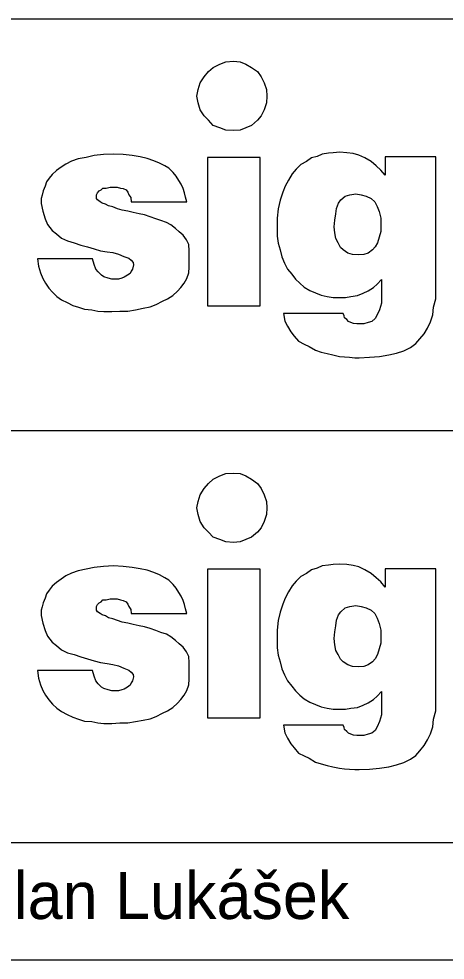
# Model space of a CAD drawing. Extents: x 2343 to 7744, y -5890 to 2050.
# Drawn here: x 6803.25 to 6821.39, y -5790 to -5750 of the extents above; entities that cross this region are included whole.
import ezdxf

# ---------------------------------------------------------------- set-up
doc = ezdxf.new("R2010")
doc.units = 0
for name, color, linetype in [('Info o rozpiskách', 7, 'Continuous'), ('popis', 7, 'Continuous'), ('Rozpiska_pole_6', 7, 'Continuous')]:
    doc.layers.add(name, color=color, linetype=linetype)

msp = doc.modelspace()

# ---------------------------------------------------------------- linework, layer by layer
at = {"layer": 'Info o rozpiskách'}
for points in [[(6812.382, -5751.803), (6812.662, -5751.822), (6812.903, -5751.922), (6813.143, -5752.063), (6813.403, -5752.243), (6813.563, -5752.463), (6813.684, -5752.724), (6813.784, -5753.004), (6813.804, -5753.285), (6813.784, -5753.565), (6813.684, -5753.866), (6813.563, -5754.126), (6813.403, -5754.306), (6813.143, -5754.527), (6812.903, -5754.627), (6812.662, -5754.727), (6812.382, -5754.747), (6812.061, -5754.727), (6811.801, -5754.627), (6811.52, -5754.527), (6811.32, -5754.306), (6811.14, -5754.126), (6810.959, -5753.866), (6810.879, -5753.565), (6810.819, -5753.285), (6810.879, -5753.004), (6810.959, -5752.724), (6811.14, -5752.463), (6811.32, -5752.243), (6811.52, -5752.063), (6811.801, -5751.922), (6812.061, -5751.822), (6812.382, -5751.803)], [(6812.382, -5769.303), (6812.662, -5769.322), (6812.903, -5769.422), (6813.143, -5769.563), (6813.403, -5769.743), (6813.563, -5769.963), (6813.684, -5770.224), (6813.784, -5770.504), (6813.804, -5770.785), (6813.784, -5771.065), (6813.684, -5771.366), (6813.563, -5771.626), (6813.403, -5771.806), (6813.143, -5772.027), (6812.903, -5772.127), (6812.662, -5772.227), (6812.382, -5772.247), (6812.061, -5772.227), (6811.801, -5772.127), (6811.52, -5772.027), (6811.32, -5771.806), (6811.14, -5771.626), (6810.959, -5771.366), (6810.879, -5771.065), (6810.819, -5770.785), (6810.879, -5770.504), (6810.959, -5770.224), (6811.14, -5769.963), (6811.32, -5769.743), (6811.52, -5769.563), (6811.801, -5769.422), (6812.061, -5769.322), (6812.382, -5769.303)]]:
    msp.add_lwpolyline(points, dxfattribs=at)
at = {"layer": 'popis'}
for points in [[(6808.034, -5757.772), (6810.398, -5757.772), (6810.338, -5757.572), (6810.298, -5757.391), (6810.238, -5757.212), (6810.158, -5757.031), (6810.057, -5756.871), (6809.938, -5756.69), (6809.818, -5756.53), (6809.637, -5756.35), (6809.457, -5756.25), (6809.237, -5756.129), (6808.996, -5756.029), (6808.716, -5755.929), (6808.415, -5755.869), (6808.075, -5755.809), (6807.694, -5755.769), (6807.274, -5755.749), (6806.853, -5755.769), (6806.452, -5755.809), (6806.112, -5755.889), (6805.771, -5755.949), (6805.49, -5756.049), (6805.25, -5756.169), (6805.05, -5756.31), (6804.849, -5756.45), (6804.669, -5756.61), (6804.549, -5756.771), (6804.428, -5756.931), (6804.369, -5757.111), (6804.288, -5757.312), (6804.249, -5757.491), (6804.208, -5757.632), (6804.208, -5757.853), (6804.268, -5758.173), (6804.369, -5758.493), (6804.469, -5758.734), (6804.669, -5758.994), (6804.849, -5759.134), (6805.069, -5759.315), (6805.33, -5759.435), (6805.61, -5759.515), (6805.891, -5759.615), (6806.172, -5759.695), (6806.452, -5759.775), (6806.732, -5759.856), (6807.013, -5759.895), (6807.253, -5759.935), (6807.494, -5759.996), (6807.714, -5760.096), (6807.934, -5760.176), (6808.034, -5760.256), (6808.115, -5760.356), (6808.135, -5760.456), (6808.094, -5760.637), (6808.034, -5760.717), (6807.994, -5760.817), (6807.874, -5760.897), (6807.734, -5760.978), (6807.634, -5761.017), (6807.494, -5761.057), (6807.353, -5761.057), (6807.213, -5761.057), (6807.053, -5761.017), (6806.872, -5760.957), (6806.772, -5760.897), (6806.632, -5760.757), (6806.532, -5760.637), (6806.452, -5760.437), (6806.392, -5760.196), (6804.048, -5760.196), (6804.088, -5760.516), (6804.168, -5760.797), (6804.268, -5761.038), (6804.388, -5761.238), (6804.529, -5761.438), (6804.689, -5761.619), (6804.869, -5761.798), (6805.069, -5761.939), (6805.31, -5762.059), (6805.55, -5762.179), (6805.791, -5762.259), (6806.051, -5762.339), (6806.352, -5762.36), (6806.612, -5762.42), (6806.872, -5762.44), (6807.213, -5762.44), (6807.554, -5762.42), (6807.894, -5762.42), (6808.215, -5762.36), (6808.535, -5762.3), (6808.835, -5762.239), (6809.096, -5762.139), (6809.357, -5761.999), (6809.577, -5761.898), (6809.797, -5761.759), (6809.998, -5761.578), (6810.138, -5761.418), (6810.278, -5761.238), (6810.398, -5761.038), (6810.478, -5760.797), (6810.499, -5760.557), (6810.499, -5760.316), (6810.499, -5760.256), (6810.499, -5760.196), (6810.499, -5760.136), (6810.499, -5760.076), (6810.499, -5759.996), (6810.499, -5759.935), (6810.499, -5759.895), (6810.499, -5759.856), (6810.478, -5759.595), (6810.378, -5759.395), (6810.238, -5759.194), (6810.078, -5759.054), (6809.918, -5758.914), (6809.718, -5758.754), (6809.537, -5758.653), (6809.297, -5758.573), (6809.076, -5758.493), (6808.835, -5758.413), (6808.596, -5758.333), (6808.375, -5758.293), (6808.115, -5758.233), (6807.894, -5758.173), (6807.654, -5758.132), (6807.453, -5758.072), (6807.253, -5757.993), (6807.073, -5757.953), (6806.933, -5757.872), (6806.793, -5757.832), (6806.712, -5757.772), (6806.593, -5757.692), (6806.552, -5757.632), (6806.552, -5757.552), (6806.552, -5757.472), (6806.593, -5757.391), (6806.672, -5757.312), (6806.753, -5757.271), (6806.832, -5757.191), (6806.973, -5757.191), (6807.133, -5757.151), (6807.274, -5757.151), (6807.434, -5757.151), (6807.574, -5757.191), (6807.694, -5757.212), (6807.814, -5757.271), (6807.894, -5757.372), (6807.934, -5757.472), (6808.015, -5757.592), (6808.034, -5757.772)], [(6811.28, -5755.889), (6811.28, -5762.2), (6813.523, -5762.2), (6813.523, -5755.889), (6811.28, -5755.889)], [(6818.832, -5755.869), (6818.832, -5756.65), (6818.651, -5756.43), (6818.451, -5756.25), (6818.231, -5756.069), (6817.97, -5755.909), (6817.71, -5755.789), (6817.47, -5755.729), (6817.209, -5755.688), (6816.909, -5755.669), (6816.628, -5755.688), (6816.428, -5755.709), (6816.148, -5755.749), (6815.947, -5755.849), (6815.707, -5755.909), (6815.487, -5756.069), (6815.246, -5756.19), (6815.046, -5756.39), (6814.885, -5756.59), (6814.725, -5756.85), (6814.585, -5757.111), (6814.485, -5757.372), (6814.365, -5757.712), (6814.285, -5758.072), (6814.244, -5758.473), (6814.244, -5758.894), (6814.244, -5759.235), (6814.285, -5759.535), (6814.365, -5759.816), (6814.445, -5760.116), (6814.545, -5760.376), (6814.685, -5760.637), (6814.866, -5760.857), (6815.026, -5761.057), (6815.206, -5761.238), (6815.387, -5761.398), (6815.626, -5761.538), (6815.867, -5761.638), (6816.107, -5761.738), (6816.368, -5761.798), (6816.628, -5761.839), (6816.909, -5761.839), (6817.15, -5761.839), (6817.37, -5761.798), (6817.65, -5761.759), (6817.891, -5761.659), (6818.111, -5761.559), (6818.331, -5761.418), (6818.491, -5761.278), (6818.672, -5761.078), (6818.672, -5761.659), (6818.672, -5762.079), (6818.591, -5762.36), (6818.491, -5762.58), (6818.411, -5762.74), (6818.271, -5762.86), (6818.111, -5762.9), (6817.931, -5762.96), (6817.731, -5762.96), (6817.63, -5762.96), (6817.49, -5762.941), (6817.37, -5762.9), (6817.269, -5762.86), (6817.209, -5762.781), (6817.109, -5762.7), (6817.089, -5762.62), (6817.049, -5762.52), (6814.505, -5762.52), (6814.565, -5762.841), (6814.685, -5763.06), (6814.825, -5763.301), (6814.966, -5763.481), (6815.146, -5763.701), (6815.387, -5763.822), (6815.607, -5763.922), (6815.867, -5764.082), (6816.107, -5764.163), (6816.368, -5764.222), (6816.609, -5764.282), (6816.889, -5764.342), (6817.109, -5764.363), (6817.31, -5764.383), (6817.55, -5764.403), (6817.731, -5764.403), (6818.171, -5764.383), (6818.591, -5764.342), (6818.992, -5764.282), (6819.313, -5764.203), (6819.633, -5764.103), (6819.914, -5763.962), (6820.134, -5763.802), (6820.314, -5763.601), (6820.495, -5763.381), (6820.635, -5763.141), (6820.755, -5762.881), (6820.855, -5762.58), (6820.895, -5762.259), (6820.995, -5761.898), (6820.995, -5761.518), (6820.995, -5761.078), (6820.995, -5755.869), (6818.832, -5755.869)], [(6817.59, -5757.432), (6817.81, -5757.472), (6818.031, -5757.532), (6818.231, -5757.632), (6818.391, -5757.772), (6818.491, -5757.972), (6818.572, -5758.193), (6818.651, -5758.473), (6818.651, -5758.774), (6818.651, -5759.034), (6818.572, -5759.275), (6818.512, -5759.515), (6818.411, -5759.695), (6818.291, -5759.816), (6818.111, -5759.956), (6817.931, -5760.016), (6817.69, -5760.035), (6817.45, -5760.016), (6817.25, -5759.956), (6817.049, -5759.816), (6816.929, -5759.715), (6816.829, -5759.515), (6816.729, -5759.335), (6816.688, -5759.094), (6816.669, -5758.834), (6816.688, -5758.553), (6816.729, -5758.293), (6816.769, -5758.053), (6816.848, -5757.832), (6816.949, -5757.692), (6817.129, -5757.532), (6817.329, -5757.472), (6817.59, -5757.432)], [(6818.832, -5773.369), (6818.832, -5774.15), (6818.651, -5773.93), (6818.451, -5773.75), (6818.231, -5773.569), (6817.97, -5773.409), (6817.71, -5773.289), (6817.47, -5773.229), (6817.209, -5773.188), (6816.909, -5773.169), (6816.628, -5773.188), (6816.428, -5773.209), (6816.148, -5773.249), (6815.947, -5773.349), (6815.707, -5773.409), (6815.487, -5773.569), (6815.246, -5773.69), (6815.046, -5773.89), (6814.885, -5774.09), (6814.725, -5774.35), (6814.585, -5774.611), (6814.485, -5774.872), (6814.365, -5775.212), (6814.285, -5775.572), (6814.244, -5775.973), (6814.244, -5776.394), (6814.244, -5776.735), (6814.285, -5777.035), (6814.365, -5777.316), (6814.445, -5777.616), (6814.545, -5777.876), (6814.685, -5778.137), (6814.866, -5778.357), (6815.026, -5778.557), (6815.206, -5778.738), (6815.387, -5778.898), (6815.626, -5779.038), (6815.867, -5779.138), (6816.107, -5779.238), (6816.368, -5779.298), (6816.628, -5779.339), (6816.909, -5779.339), (6817.15, -5779.339), (6817.37, -5779.298), (6817.65, -5779.259), (6817.891, -5779.159), (6818.111, -5779.059), (6818.331, -5778.918), (6818.491, -5778.778), (6818.672, -5778.578), (6818.672, -5779.159), (6818.672, -5779.579), (6818.591, -5779.86), (6818.491, -5780.08), (6818.411, -5780.24), (6818.271, -5780.36), (6818.111, -5780.4), (6817.931, -5780.46), (6817.731, -5780.46), (6817.63, -5780.46), (6817.49, -5780.441), (6817.37, -5780.4), (6817.269, -5780.36), (6817.209, -5780.281), (6817.109, -5780.2), (6817.089, -5780.12), (6817.049, -5780.02), (6814.505, -5780.02), (6814.565, -5780.341), (6814.685, -5780.56), (6814.825, -5780.801), (6814.966, -5780.981), (6815.146, -5781.201), (6815.387, -5781.322), (6815.607, -5781.422), (6815.867, -5781.582), (6816.107, -5781.663), (6816.368, -5781.722), (6816.609, -5781.782), (6816.889, -5781.842), (6817.109, -5781.863), (6817.31, -5781.883), (6817.55, -5781.903), (6817.731, -5781.903), (6818.171, -5781.883), (6818.591, -5781.842), (6818.992, -5781.782), (6819.313, -5781.703), (6819.633, -5781.603), (6819.914, -5781.462), (6820.134, -5781.302), (6820.314, -5781.101), (6820.495, -5780.881), (6820.635, -5780.641), (6820.755, -5780.381), (6820.855, -5780.08), (6820.895, -5779.759), (6820.995, -5779.398), (6820.995, -5779.018), (6820.995, -5778.578), (6820.995, -5773.369), (6818.832, -5773.369)], [(6808.034, -5775.272), (6810.398, -5775.272), (6810.338, -5775.072), (6810.298, -5774.891), (6810.238, -5774.712), (6810.158, -5774.531), (6810.057, -5774.371), (6809.938, -5774.19), (6809.818, -5774.03), (6809.637, -5773.85), (6809.457, -5773.75), (6809.237, -5773.629), (6808.996, -5773.529), (6808.716, -5773.429), (6808.415, -5773.369), (6808.075, -5773.309), (6807.694, -5773.269), (6807.274, -5773.249), (6806.853, -5773.269), (6806.452, -5773.309), (6806.112, -5773.389), (6805.771, -5773.449), (6805.49, -5773.549), (6805.25, -5773.669), (6805.05, -5773.81), (6804.849, -5773.95), (6804.669, -5774.11), (6804.549, -5774.271), (6804.428, -5774.431), (6804.369, -5774.611), (6804.288, -5774.812), (6804.249, -5774.991), (6804.208, -5775.132), (6804.208, -5775.353), (6804.268, -5775.673), (6804.369, -5775.993), (6804.469, -5776.234), (6804.669, -5776.494), (6804.849, -5776.634), (6805.069, -5776.815), (6805.33, -5776.935), (6805.61, -5777.015), (6805.891, -5777.115), (6806.172, -5777.195), (6806.452, -5777.275), (6806.732, -5777.356), (6807.013, -5777.395), (6807.253, -5777.435), (6807.494, -5777.496), (6807.714, -5777.596), (6807.934, -5777.676), (6808.034, -5777.756), (6808.115, -5777.856), (6808.135, -5777.956), (6808.094, -5778.137), (6808.034, -5778.217), (6807.994, -5778.317), (6807.874, -5778.397), (6807.734, -5778.478), (6807.634, -5778.517), (6807.494, -5778.557), (6807.353, -5778.557), (6807.213, -5778.557), (6807.053, -5778.517), (6806.872, -5778.457), (6806.772, -5778.397), (6806.632, -5778.257), (6806.532, -5778.137), (6806.452, -5777.937), (6806.392, -5777.696), (6804.048, -5777.696), (6804.088, -5778.016), (6804.168, -5778.297), (6804.268, -5778.538), (6804.388, -5778.738), (6804.529, -5778.938), (6804.689, -5779.119), (6804.869, -5779.298), (6805.069, -5779.439), (6805.31, -5779.559), (6805.55, -5779.679), (6805.791, -5779.759), (6806.051, -5779.839), (6806.352, -5779.86), (6806.612, -5779.92), (6806.872, -5779.94), (6807.213, -5779.94), (6807.554, -5779.92), (6807.894, -5779.92), (6808.215, -5779.86), (6808.535, -5779.8), (6808.835, -5779.739), (6809.096, -5779.639), (6809.357, -5779.499), (6809.577, -5779.398), (6809.797, -5779.259), (6809.998, -5779.078), (6810.138, -5778.918), (6810.278, -5778.738), (6810.398, -5778.538), (6810.478, -5778.297), (6810.499, -5778.057), (6810.499, -5777.816), (6810.499, -5777.756), (6810.499, -5777.696), (6810.499, -5777.636), (6810.499, -5777.576), (6810.499, -5777.496), (6810.499, -5777.435), (6810.499, -5777.395), (6810.499, -5777.356), (6810.478, -5777.095), (6810.378, -5776.895), (6810.238, -5776.694), (6810.078, -5776.554), (6809.918, -5776.414), (6809.718, -5776.254), (6809.537, -5776.153), (6809.297, -5776.073), (6809.076, -5775.993), (6808.835, -5775.913), (6808.596, -5775.833), (6808.375, -5775.793), (6808.115, -5775.733), (6807.894, -5775.673), (6807.654, -5775.632), (6807.453, -5775.572), (6807.253, -5775.493), (6807.073, -5775.453), (6806.933, -5775.372), (6806.793, -5775.332), (6806.712, -5775.272), (6806.593, -5775.192), (6806.552, -5775.132), (6806.552, -5775.052), (6806.552, -5774.972), (6806.593, -5774.891), (6806.672, -5774.812), (6806.753, -5774.771), (6806.832, -5774.691), (6806.973, -5774.691), (6807.133, -5774.651), (6807.274, -5774.651), (6807.434, -5774.651), (6807.574, -5774.691), (6807.694, -5774.712), (6807.814, -5774.771), (6807.894, -5774.872), (6807.934, -5774.972), (6808.015, -5775.092), (6808.034, -5775.272)], [(6811.28, -5773.389), (6811.28, -5779.7), (6813.523, -5779.7), (6813.523, -5773.389), (6811.28, -5773.389)], [(6817.59, -5774.932), (6817.81, -5774.972), (6818.031, -5775.032), (6818.231, -5775.132), (6818.391, -5775.272), (6818.491, -5775.472), (6818.572, -5775.693), (6818.651, -5775.973), (6818.651, -5776.274), (6818.651, -5776.534), (6818.572, -5776.775), (6818.512, -5777.015), (6818.411, -5777.195), (6818.291, -5777.316), (6818.111, -5777.456), (6817.931, -5777.516), (6817.69, -5777.535), (6817.45, -5777.516), (6817.25, -5777.456), (6817.049, -5777.316), (6816.929, -5777.215), (6816.829, -5777.015), (6816.729, -5776.835), (6816.688, -5776.594), (6816.669, -5776.334), (6816.688, -5776.053), (6816.729, -5775.793), (6816.769, -5775.553), (6816.848, -5775.332), (6816.949, -5775.192), (6817.129, -5775.032), (6817.329, -5774.972), (6817.59, -5774.932)]]:
    msp.add_lwpolyline(points, dxfattribs=at)
at = {"layer": 'Rozpiska_pole_6'}
for p, q in [((6690, -5767.5), (6860, -5767.5)), ((6690, -5785), (6860, -5785))]:
    msp.add_line(p, q, dxfattribs=at)
msp.add_lwpolyline([(6690, -5750), (6860, -5750), (6860, -5790), (6690, -5790)], close=True, dxfattribs=at)

# ---------------------------------------------------------------- texts
msp.add_text('Ing. Milan Lukášek', height=2, dxfattribs=at).set_placement((6795.009, -5788.25))

doc.saveas('drawing.dxf')
